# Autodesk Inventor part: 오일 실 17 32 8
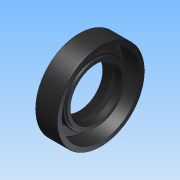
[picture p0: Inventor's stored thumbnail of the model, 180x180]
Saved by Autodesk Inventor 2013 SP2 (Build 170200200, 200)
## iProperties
Created: 2026-07
Part Number: 오일 실 17 32 8
Material: Generic
Document SubType Name: Modeling
Designer: aa
Density: 1 g/cm^3
변환 표준: STEP AP214IS
전처리기: Build: 200, Release: 2013 SP2 Update 6 - Date: Thu 07/17/2014
전송 단위: 밀리미터
불확실성: 0.01
Author: aa
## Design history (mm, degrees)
node "오일 실 17 32 81"
body "Solid1"
node "기준1"
